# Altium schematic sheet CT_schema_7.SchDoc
size 372 x 335 mm
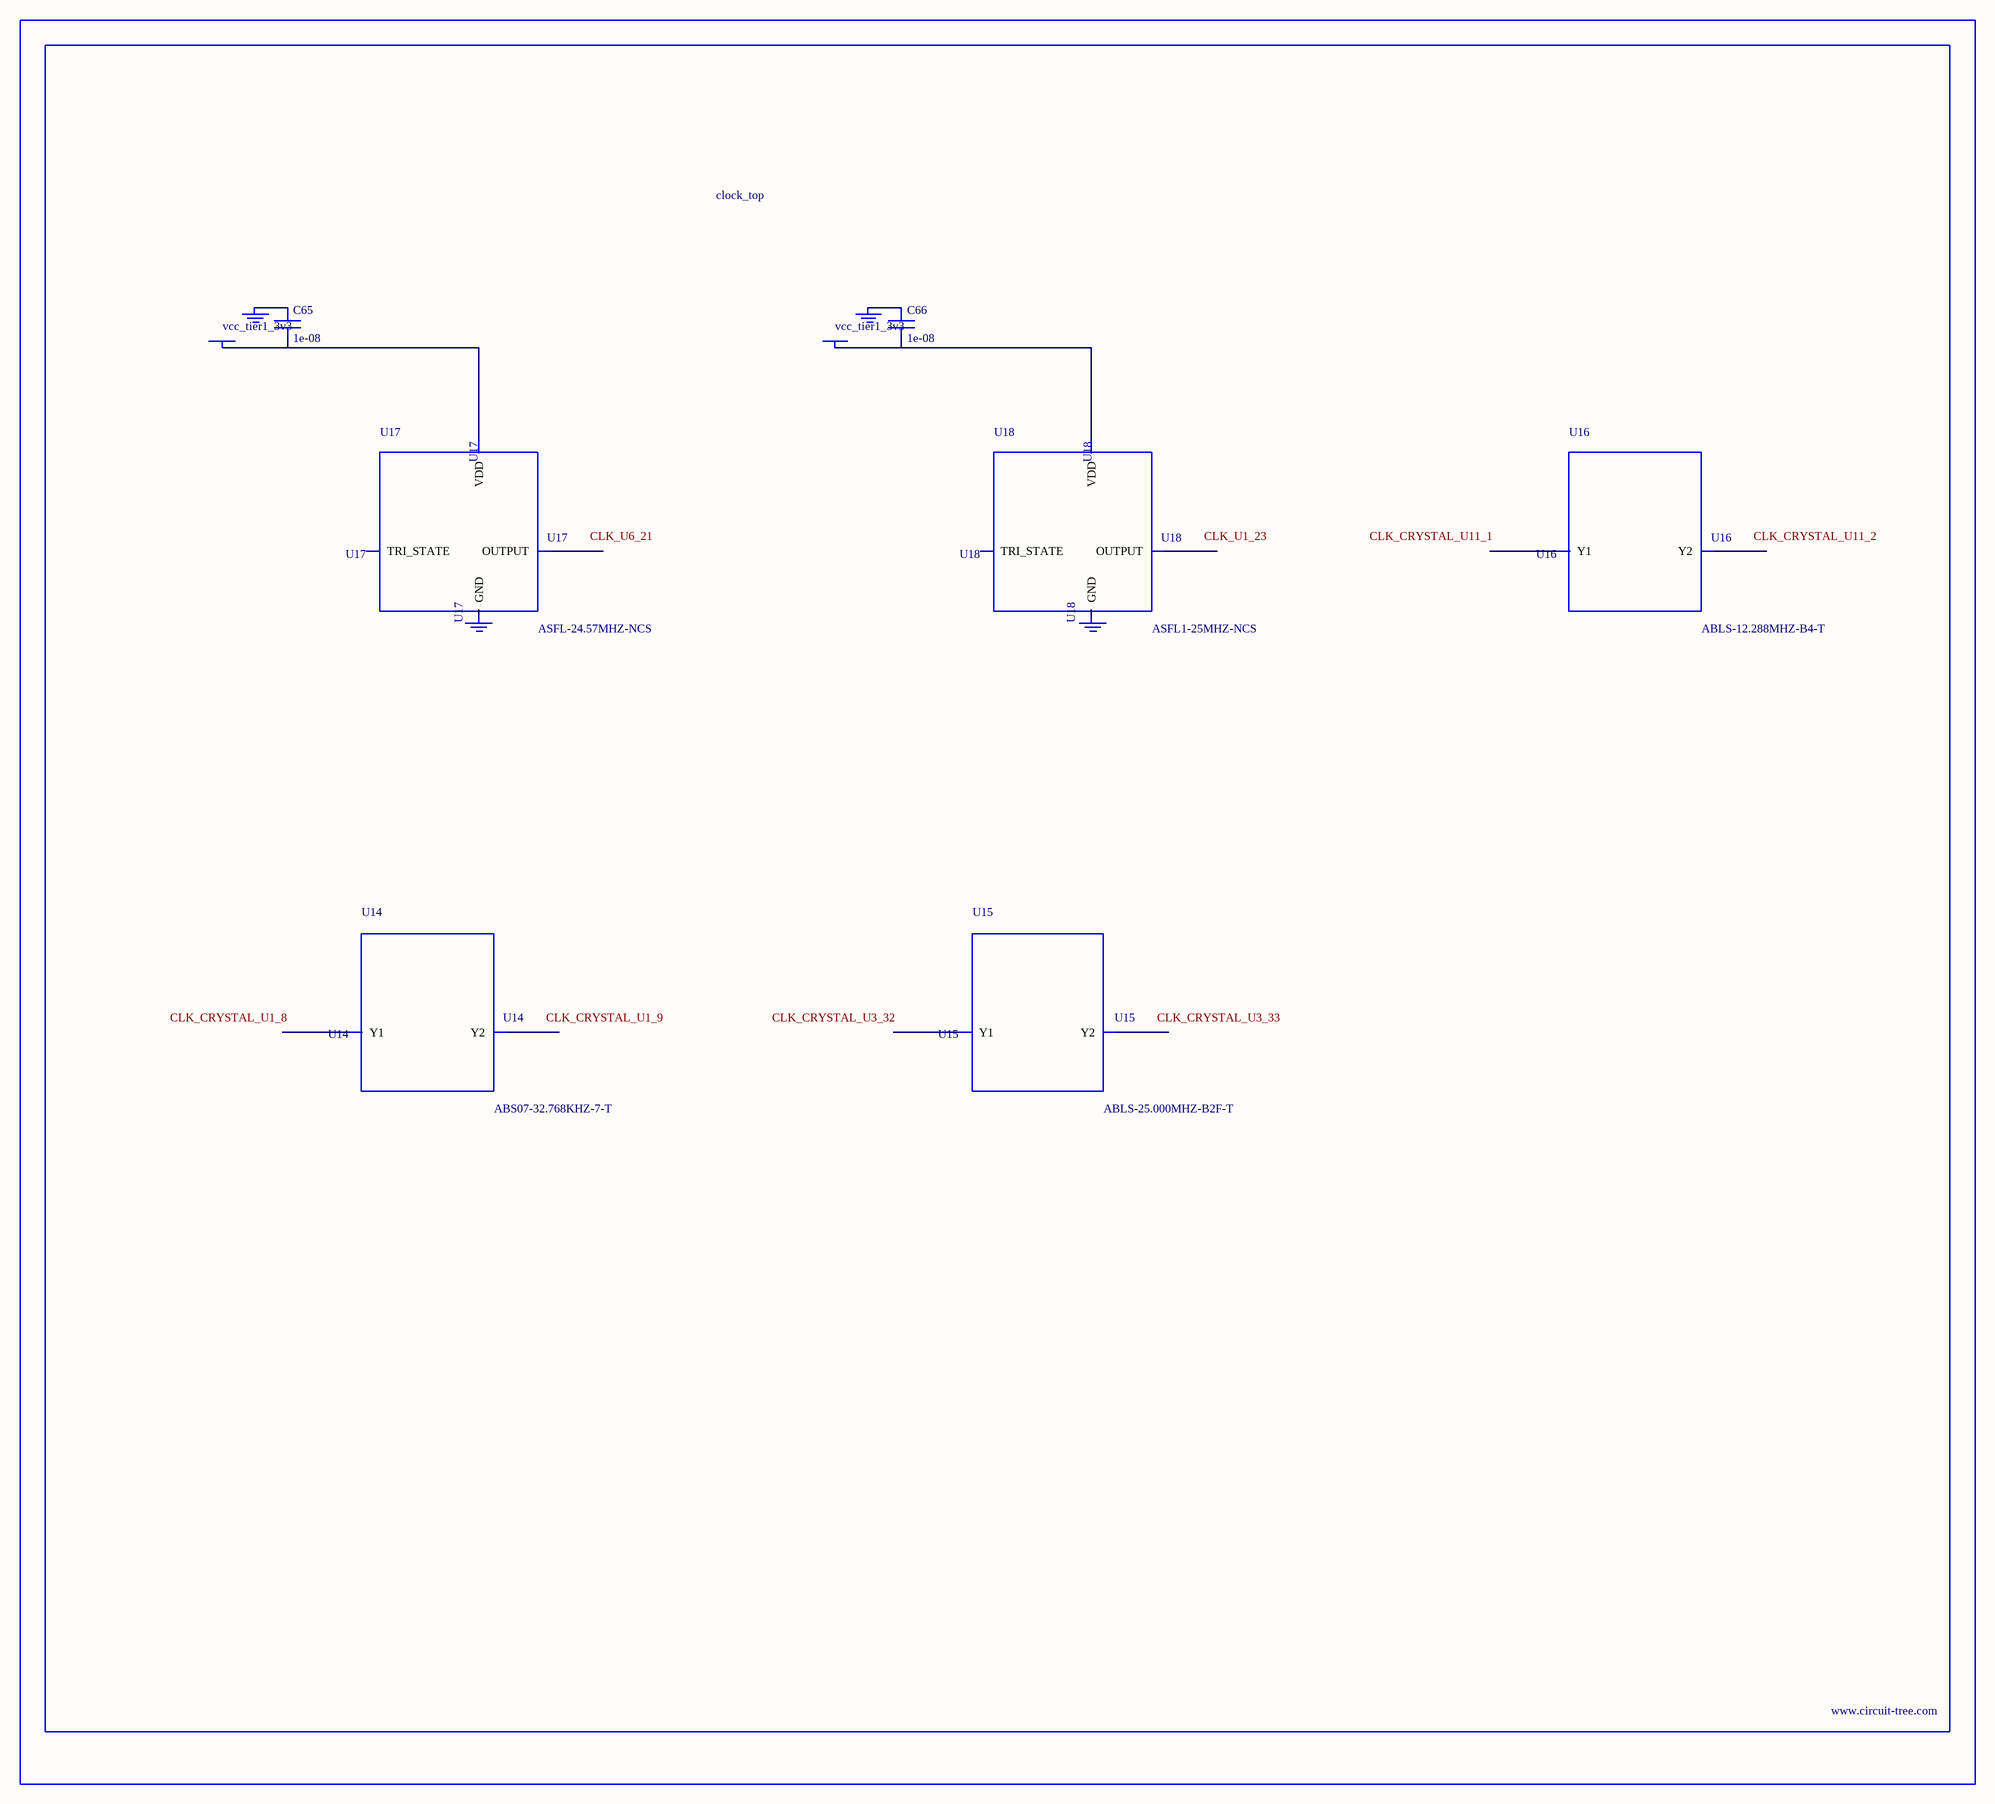
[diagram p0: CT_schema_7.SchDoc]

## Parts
BORDER6  (no value)
C65  1e-08  [C0402]
C66  1e-08  [C0402]
GND_INSTANCE_6_0  (no value)
GND_INSTANCE_6_1  (no value)
GND_INSTANCE_6_2  (no value)
GND_INSTANCE_6_3  (no value)
POWER_INSTANCE_6_0  vcc_tier1_3v3
POWER_INSTANCE_6_1  vcc_tier1_3v3
U14  ABS07-32.768KHZ-7-T  [ABS07-32.768KHZ-7-T]
U15  ABLS-25.000MHZ-B2F-T  [ABLS-25.000MHZ-B2F-T]
U16  ABLS-12.288MHZ-B4-T  [ABLS-12.288MHZ-B4-T]
U17  ASFL-24.57MHZ-NCS  [ASFL1]
U18  ASFL1-25MHZ-NCS  [ASFL1]

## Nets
NetC65_1: C65.1 GND_INSTANCE_6_0.0(GND)
NetC65_2: C65.2 POWER_INSTANCE_6_0.0(PWR) U17.4(VDD)
NetC66_1: C66.1 GND_INSTANCE_6_2.0(GND)
NetC66_2: C66.2 POWER_INSTANCE_6_1.0(PWR) U18.4(VDD)

Not connected (* = marked no-connect by the designer): GND_INSTANCE_6_1 0(GND); GND_INSTANCE_6_3 0(GND); U14 1(Y1) 2(Y2); U15 1(Y1) 2(Y2); U16 1(Y1) 2(Y2); U17 1(TRI_STATE) 2(GND) 3(OUTPUT); U18 1(TRI_STATE) 2(GND) 3(OUTPUT)

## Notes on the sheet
- Labels drawn without touching a wire or pin: CLK_CRYSTAL_U1_8, CLK_CRYSTAL_U1_9, CLK_CRYSTAL_U3_32, CLK_CRYSTAL_U3_33, CLK_CRYSTAL_U11_1, CLK_CRYSTAL_U11_2, CLK_U1_23, CLK_U6_21

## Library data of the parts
BORDER6 = BORDER_PAGE6
C65 C66 = C0402C103K3RAC
GND_INSTANCE_6_0-GND_INSTANCE_6_3 = GND
POWER_INSTANCE_6_0 POWER_INSTANCE_6_1 = PWR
